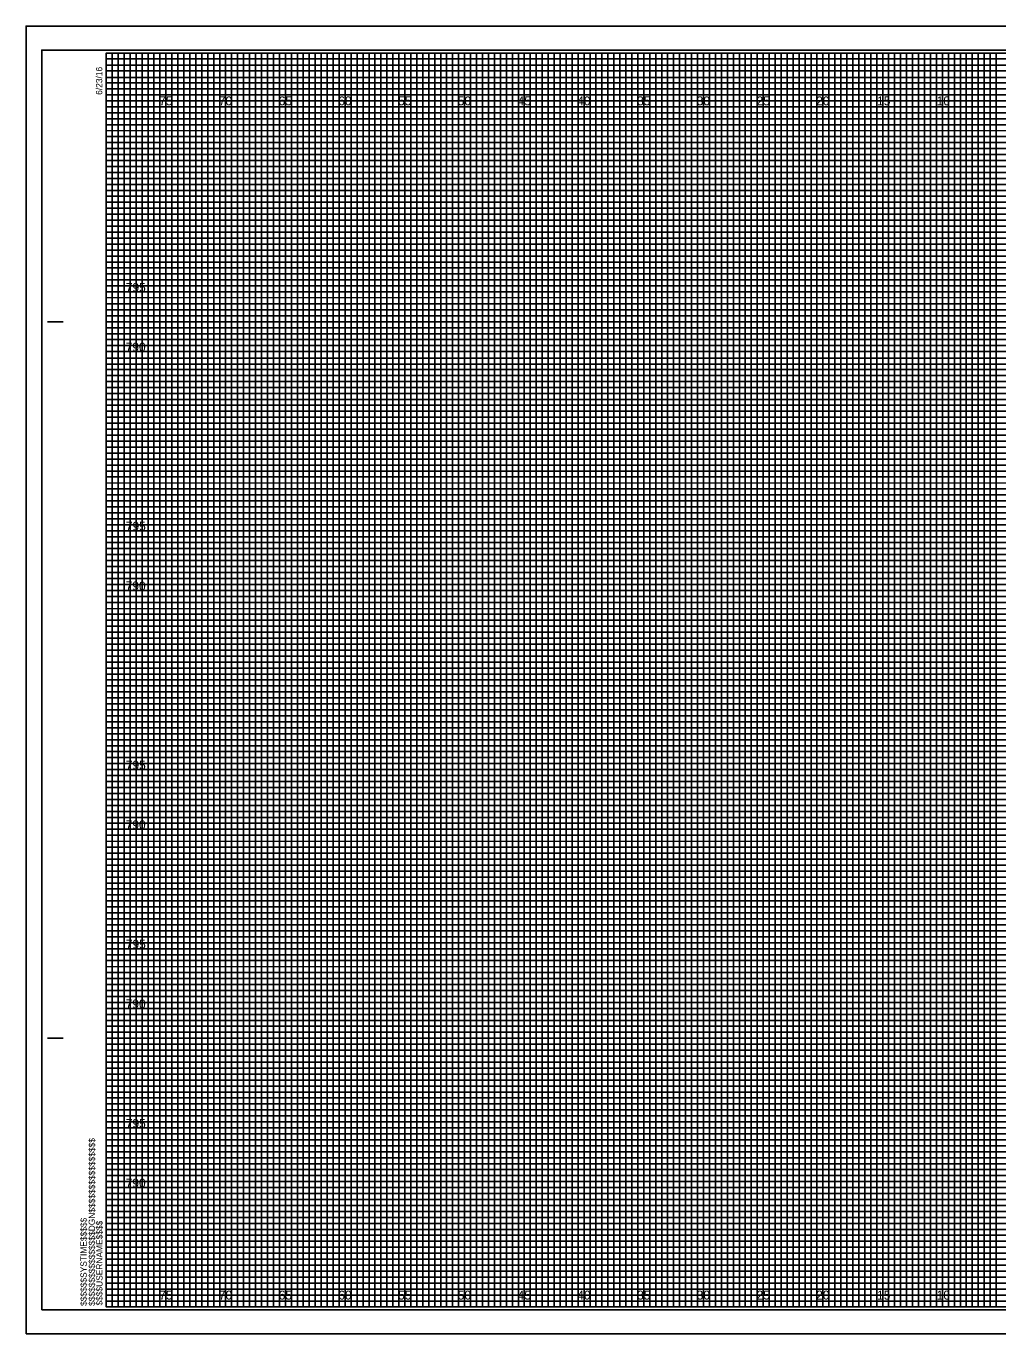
# Model space of a CAD drawing. Extents: x -7 to 162, y -2 to 107.
# Drawn here: x -6.7 to 74.6, y -2.3 to 107.3 of the extents above; entities that cross this region are included whole.
import ezdxf

# ---------------------------------------------------------------- set-up
doc = ezdxf.new("R2010")
doc.units = 0
for name, color, linetype in [('Exist Cross Section Cell', 7, 'Continuous'), ('Exist XS Center Line Elevation Label', 7, 'Continuous'), ('Prop CMT Pvmt Course 2 Wedge', 7, 'Continuous'), ('Prop XS Elevation Labels', 7, 'Continuous'), ('Prop XS Hydro Elevations', 7, 'Continuous'), ('Prop XS SE Text', 7, 'Continuous'), ('Prop XS Side Slope Text', 7, 'Continuous'), ('Sheet Cutting Line CELL', 7, 'Continuous'), ('Sheet DOT Grid CELL', 7, 'Continuous'), ('Sheet Plot Border Inside CELL', 7, 'Continuous'), ('Sheet Plot Border Outside CELL', 7, 'Continuous')]:
    doc.layers.add(name, color=color, linetype=linetype)

msp = doc.modelspace()

# ---------------------------------------------------------------- linework, layer by layer
at = {"layer": 'Exist Cross Section Cell'}
for p, q in [((5, 105), (0, 105)), ((5, 0), (5, 105)), ((15, 105), (10, 105)), ((10, 105), (10, 0)), ((15, 0), (15, 105)), ((25, 105), (20, 105)), ((20, 105), (20, 0)), ((25, 0), (25, 105)), ((35, 105), (30, 105)), ((30, 105), (30, 0)), ((35, 0), (35, 105)), ((45, 105), (40, 105)), ((40, 105), (40, 0)), ((45, 0), (45, 105)), ((55, 105), (50, 105)), ((50, 105), (50, 0)), ((55, 0), (55, 105)), ((65, 105), (60, 105)), ((60, 105), (60, 0)), ((65, 0), (65, 105)), ((75, 105), (70, 105)), ((70, 105), (70, 0)), ((10, 0), (5, 0)), ((20, 0), (15, 0)), ((30, 0), (25, 0)), ((40, 0), (35, 0)), ((50, 0), (45, 0)), ((60, 0), (55, 0)), ((70, 0), (65, 0))]:
    msp.add_line(p, q, dxfattribs=at)
for points in [[(0, 100), (160, 100), (160, 95), (0, 95)], [(0, 90), (160, 90), (160, 85), (0, 85)], [(0, 80), (160, 80), (160, 75), (0, 75)], [(0, 70), (160, 70), (160, 65), (0, 65)], [(0, 60), (160, 60), (160, 55), (0, 55)], [(0, 50), (160, 50), (160, 45), (0, 45)], [(0, 40), (160, 40), (160, 35), (0, 35)], [(0, 30), (160, 30), (160, 25), (0, 25)], [(0, 20), (160, 20), (160, 15), (0, 15)], [(0, 10), (160, 10), (160, 5), (0, 5)]]:
    msp.add_lwpolyline(points, dxfattribs=at)
at = {"layer": 'Exist XS Center Line Elevation Label'}
for points in [[(0, 105), (2.5, 105), (2.5, 0), (7.5, 0), (7.5, 105), (12.5, 105), (12.5, 0), (17.5, 0), (17.5, 105), (22.5, 105), (22.5, 0), (27.5, 0), (27.5, 105), (32.5, 105), (32.5, 0), (37.5, 0), (37.5, 105), (42.5, 105), (42.5, 0), (47.5, 0), (47.5, 105), (52.5, 105), (52.5, 0), (57.5, 0), (57.5, 105), (62.5, 105), (62.5, 0), (67.5, 0), (67.5, 105), (72.5, 105), (72.5, 0), (77.5, 0)], [(0, 102.5), (137.5, 102.5)], [(0, 92.5), (160, 92.5), (160, 97.5), (0, 97.5)], [(0, 82.5), (160, 82.5), (160, 87.5), (0, 87.5)], [(0, 72.5), (160, 72.5), (160, 77.5), (0, 77.5)], [(0, 62.5), (160, 62.5), (160, 67.5), (0, 67.5)], [(0, 52.5), (160, 52.5), (160, 57.5), (0, 57.5)], [(0, 42.5), (160, 42.5), (160, 47.5), (0, 47.5)], [(0, 32.5), (160, 32.5), (160, 37.5), (0, 37.5)], [(0, 22.5), (160, 22.5), (160, 27.5), (0, 27.5)], [(0, 12.5), (160, 12.5), (160, 17.5), (0, 17.5)], [(0, 2.5), (160, 2.5), (160, 7.5), (0, 7.5)]]:
    msp.add_lwpolyline(points, dxfattribs=at)
at = {"layer": 'Prop CMT Pvmt Course 2 Wedge'}
for points in [[(0, 0), (0.5, 0), (0.5, 105), (1, 105), (1, 0)], [(1, 0), (1.5, 0), (1.5, 105), (2, 105), (2, 0)], [(2.5, 0), (3, 0), (3, 105), (3.5, 105), (3.5, 0)], [(3.5, 0), (4, 0), (4, 105), (4.5, 105), (4.5, 0)], [(5, 0), (5.5, 0), (5.5, 105), (6, 105), (6, 0)], [(6, 0), (6.5, 0), (6.5, 105), (7, 105), (7, 0)], [(7.5, 0), (8, 0), (8, 105), (8.5, 105), (8.5, 0)], [(8.5, 0), (9, 0), (9, 105), (9.5, 105), (9.5, 0)], [(10, 0), (10.5, 0), (10.5, 105), (11, 105), (11, 0)], [(11, 0), (11.5, 0), (11.5, 105), (12, 105), (12, 0)], [(12.5, 0), (13, 0), (13, 105), (13.5, 105), (13.5, 0)], [(13.5, 0), (14, 0), (14, 105), (14.5, 105), (14.5, 0)], [(15, 0), (15.5, 0), (15.5, 105), (16, 105), (16, 0)], [(16, 0), (16.5, 0), (16.5, 105), (17, 105), (17, 0)], [(17.5, 0), (18, 0), (18, 105), (18.5, 105), (18.5, 0)], [(18.5, 0), (19, 0), (19, 105), (19.5, 105), (19.5, 0)], [(20, 0), (20.5, 0), (20.5, 105), (21, 105), (21, 0)], [(21, 0), (21.5, 0), (21.5, 105), (22, 105), (22, 0)], [(22.5, 0), (23, 0), (23, 105), (23.5, 105), (23.5, 0)], [(23.5, 0), (24, 0), (24, 105), (24.5, 105), (24.5, 0)], [(25, 0), (25.5, 0), (25.5, 105), (26, 105), (26, 0)], [(26, 0), (26.5, 0), (26.5, 105), (27, 105), (27, 0)], [(27.5, 0), (28, 0), (28, 105), (28.5, 105), (28.5, 0)], [(28.5, 0), (29, 0), (29, 105), (29.5, 105), (29.5, 0)], [(30, 0), (30.5, 0), (30.5, 105), (31, 105), (31, 0)], [(31, 0), (31.5, 0), (31.5, 105), (32, 105), (32, 0)], [(32.5, 0), (33, 0), (33, 105), (33.5, 105), (33.5, 0)], [(33.5, 0), (34, 0), (34, 105), (34.5, 105), (34.5, 0)], [(35, 0), (35.5, 0), (35.5, 105), (36, 105), (36, 0)], [(36, 0), (36.5, 0), (36.5, 105), (37, 105), (37, 0)], [(37.5, 0), (38, 0), (38, 105), (38.5, 105), (38.5, 0)], [(38.5, 0), (39, 0), (39, 105), (39.5, 105), (39.5, 0)], [(40, 0), (40.5, 0), (40.5, 105), (41, 105), (41, 0)], [(41, 0), (41.5, 0), (41.5, 105), (42, 105), (42, 0)], [(42.5, 0), (43, 0), (43, 105), (43.5, 105), (43.5, 0)], [(43.5, 0), (44, 0), (44, 105), (44.5, 105), (44.5, 0)], [(45, 0), (45.5, 0), (45.5, 105), (46, 105), (46, 0)], [(46, 0), (46.5, 0), (46.5, 105), (47, 105), (47, 0)], [(47.5, 0), (48, 0), (48, 105), (48.5, 105), (48.5, 0)], [(48.5, 0), (49, 0), (49, 105), (49.5, 105), (49.5, 0)], [(50, 0), (50.5, 0), (50.5, 105), (51, 105), (51, 0)], [(51, 0), (51.5, 0), (51.5, 105), (52, 105), (52, 0)], [(52.5, 0), (53, 0), (53, 105), (53.5, 105), (53.5, 0)], [(53.5, 0), (54, 0), (54, 105), (54.5, 105), (54.5, 0)], [(55, 0), (55.5, 0), (55.5, 105), (56, 105), (56, 0)], [(56, 0), (56.5, 0), (56.5, 105), (57, 105), (57, 0)], [(57.5, 0), (58, 0), (58, 105), (58.5, 105), (58.5, 0)], [(58.5, 0), (59, 0), (59, 105), (59.5, 105), (59.5, 0)], [(60, 0), (60.5, 0), (60.5, 105), (61, 105), (61, 0)], [(61, 0), (61.5, 0), (61.5, 105), (62, 105), (62, 0)], [(62.5, 0), (63, 0), (63, 105), (63.5, 105), (63.5, 0)], [(63.5, 0), (64, 0), (64, 105), (64.5, 105), (64.5, 0)], [(65, 0), (65.5, 0), (65.5, 105), (66, 105), (66, 0)], [(66, 0), (66.5, 0), (66.5, 105), (67, 105), (67, 0)], [(67.5, 0), (68, 0), (68, 105), (68.5, 105), (68.5, 0)], [(68.5, 0), (69, 0), (69, 105), (69.5, 105), (69.5, 0)], [(70, 0), (70.5, 0), (70.5, 105), (71, 105), (71, 0)], [(71, 0), (71.5, 0), (71.5, 105), (72, 105), (72, 0)], [(72.5, 0), (73, 0), (73, 105), (73.5, 105), (73.5, 0)], [(73.5, 0), (74, 0), (74, 105), (74.5, 105), (74.5, 0)]]:
    msp.add_lwpolyline(points, dxfattribs=at)
at = {"layer": 'Prop XS Hydro Elevations'}
for p, q in [((-4.9, 82.5), (-3.65, 82.5)), ((-4.85, 82.5), (-3.6, 82.5)), ((-4.9, 22.5), (-3.65, 22.5)), ((-4.85, 22.5), (-3.6, 22.5)), ((0, 0), (0, 0)), ((0, 0), (0, 0)), ((0, 0), (0, 0)), ((0, 0), (0, 0)), ((0, 0), (0, 0)), ((0, 0), (0, 0)), ((0, 0), (0, 0))]:
    msp.add_line(p, q, dxfattribs=at)
msp.add_lwpolyline([(160, 105), (0, 105), (0, 0), (160, 0)], close=True, dxfattribs=at)
at = {"layer": 'Prop XS Side Slope Text'}
for p, q in [((0, 104.5), (130, 104.5)), ((130, 103.99), (0, 103.99)), ((0, 103.99), (0, 103.5)), ((0, 103.5), (130, 103.5)), ((130, 102.95), (0, 102.95)), ((0, 102.95), (0, 102)), ((0, 102), (160, 102))]:
    msp.add_line(p, q, dxfattribs=at)
for points in [[(0, 101.5), (135, 101.5), (160, 101.5), (160, 101), (0, 101)], [(0, 100.5), (160, 100.5), (160, 99.5), (0, 99.5)], [(0, 99), (160, 99), (160, 98.5), (0, 98.49)], [(0, 98), (160, 98), (160, 97), (0, 97)], [(0, 96.5), (160, 96.5), (160, 96), (0, 96)], [(0, 95.5), (160, 95.5), (160, 94.5), (0, 94.5)], [(0, 94), (160, 94), (160, 93.5), (0, 93.5)], [(0, 93), (160, 93), (160, 92), (0, 92)], [(0, 91.5), (160, 91.5), (160, 91), (0, 91)], [(0, 90.5), (160, 90.5), (160, 89.5), (0, 89.5)], [(0, 89), (160, 89), (160, 88.5), (0, 88.5)], [(0, 88), (160, 88), (160, 86.98), (160, 86.5), (160, 86), (0, 86)], [(0, 87), (160, 87), (160, 86.5), (0, 86.5)], [(0, 85.5), (160, 85.5), (160, 84.5), (0, 84.52)], [(0, 84.52), (160, 84.5), (160, 84), (0, 84)], [(0, 83.5), (160, 83.5), (160, 83), (0, 83)], [(0, 82), (160, 82), (160, 81.5), (0, 81.5)], [(0, 81), (160, 81), (160, 80.5), (0, 80.5)], [(-0.04, 79.45), (160, 79.45), (160, 78.94), (-0.04, 78.94)], [(0, 78.5), (160, 78.5), (160, 78), (0, 78)], [(0, 77), (160, 77), (160, 76.5), (0, 76.5)], [(0, 76), (160, 76), (160, 75.5), (0, 75.5)], [(0, 74.5), (160, 74.5), (160, 74), (0, 74)], [(0, 73.5), (160, 73.5), (160, 73), (0, 73)], [(0, 72), (160, 72), (160, 71.5), (0, 71.5)], [(0, 71), (160, 71), (160, 70.5), (0, 70.5)], [(0, 69.5), (160, 69.5), (160, 68.99), (0, 69)], [(0, 68.5), (160, 68.5), (160, 68), (0, 68)], [(0, 67), (160, 67), (160, 66.5), (0, 66.5)], [(0, 66), (160, 66), (160, 65.5), (0, 65.5)], [(0, 64.5), (160, 64.5), (160, 64), (0, 64)], [(0, 63.5), (160, 63.5), (160, 63), (0, 63)], [(0, 62), (160, 62), (160, 61.5), (0, 61.5)], [(0, 61), (160, 61), (160, 60.5), (0, 60.5)], [(0, 59.5), (160, 59.5), (160, 59), (0, 59)], [(0, 58.5), (160.03, 58.45), (160, 58), (0, 58)], [(0, 57), (160, 57), (160, 56.5), (0, 56.5)], [(0, 56), (160, 56), (160, 55.5), (0, 55.5)], [(0, 54.5), (160, 54.5), (160, 54), (0, 54)], [(0, 53.5), (160, 53.5), (160, 53), (0, 53)], [(0, 52), (160, 52), (160, 51.5), (0, 51.5)], [(0, 51), (160, 51), (160, 50.5), (0, 50.5)], [(0, 49.5), (160, 49.5), (160, 49), (0, 49)], [(0, 48.5), (160, 48.5), (160, 48), (0, 48)], [(0, 47), (160, 47), (160, 46.5), (0, 46.5)], [(0, 46), (160, 46), (160, 45.5), (0, 45.5)], [(0, 44.5), (160, 44.5), (160, 44), (0, 44)], [(0, 43.5), (160, 43.5), (160, 43), (0, 43)], [(0, 42), (160, 42), (160, 41.5), (0, 41.5)], [(0, 41), (160, 41), (160, 40.5), (0, 40.5)], [(0, 39.5), (160, 39.5), (160, 38.99), (0, 39)], [(0, 38.5), (160, 38.5), (160, 38), (0, 38)], [(0, 37), (160, 37), (160, 36.5), (0, 36.5)], [(0, 36), (160, 36), (160, 35.5), (0, 35.5)], [(0, 34.5), (160, 34.5), (160, 34), (0, 34)], [(0, 33.5), (160, 33.5), (160, 33), (0, 33)], [(0, 32), (160, 32), (160, 31.5), (0, 31.5)], [(0, 31), (160, 31), (160, 30.5), (0, 30.5)], [(0, 29.5), (160, 29.5), (160, 29), (0, 29)], [(0, 28.5), (160.03, 28.46), (160, 28), (0, 28)], [(0, 27), (160, 27), (160, 26.5), (0, 26.5)], [(0, 26), (160, 26), (160, 25.5), (0, 25.5)], [(0, 24.5), (160, 24.5), (160, 24), (0, 24)], [(0, 23.5), (160, 23.5), (160, 23), (0, 23)], [(0, 22), (160, 22), (160, 21.5), (0, 21.5)], [(0, 21), (160, 21), (160, 20.5), (0, 20.5)], [(0, 19.5), (160, 19.5), (160, 19), (0, 19)], [(0, 18.5), (160, 18.5), (160, 18), (0, 18)], [(0, 17), (160, 17), (160, 16.5), (0, 16.5)], [(0, 16), (160, 16), (160, 15.5), (0, 15.5)], [(0, 14.5), (160, 14.5), (160, 14), (0, 14)], [(0, 13.5), (160, 13.5), (160, 13), (0, 13)], [(0, 12), (160, 12), (160, 11.5), (0, 11.5)], [(0, 11), (160, 11), (160, 10.5), (0, 10.5)], [(0, 9.5), (160, 9.5), (160, 9), (0, 9)], [(0, 8.5), (160, 8.5), (160, 8), (0, 8)], [(0, 7), (160, 7), (160, 6.5), (0, 6.5)], [(0, 6), (160, 6), (160, 5.5), (0, 5.5)], [(0, 4.5), (160, 4.5), (160, 4), (0, 4)], [(0, 3.5), (160, 3.5), (160, 3), (0, 3)], [(0, 2), (160, 2), (160, 1.5), (0, 1.5)], [(0, 1), (160, 1), (160, 0.5), (0, 0.5)]]:
    msp.add_lwpolyline(points, dxfattribs=at)
at = {"layer": 'Sheet Cutting Line CELL'}
for p, q in [((161.65, 107.25), (-6.7, 107.25)), ((-6.7, 107.25), (-6.7, -2.25)), ((-6.7, -2.25), (161.65, -2.25))]:
    msp.add_line(p, q, dxfattribs=at)
at = {"layer": 'Sheet DOT Grid CELL'}
for p, q in [((5, 0), (5, 105)), ((10, 0), (10, 105)), ((15, 0), (15, 105)), ((20, 0), (20, 105)), ((25, 0), (25, 105)), ((30, 0), (30, 105)), ((35, 0), (35, 105)), ((40, 0), (40, 105)), ((45, 0), (45, 105)), ((50, 0), (50, 105)), ((55, 0), (55, 105)), ((60, 0), (60, 105)), ((65, 0), (65, 105)), ((70, 0), (70, 105)), ((0, 100), (160, 100)), ((0, 95), (160, 95)), ((0, 90), (160, 90)), ((0, 85), (160, 85)), ((0, 80), (160, 80)), ((0, 75), (160, 75)), ((0, 70), (160, 70)), ((0, 65), (160, 65)), ((0, 60), (160, 60)), ((0, 55), (160, 55)), ((0, 50), (160, 50)), ((0, 45), (160, 45)), ((0, 40), (160, 40)), ((0, 35), (160, 35)), ((0, 30), (160, 30)), ((0, 25), (160, 25)), ((0, 20), (160, 20)), ((0, 15), (160, 15)), ((0, 10), (160, 10)), ((0, 5), (160, 5))]:
    msp.add_line(p, q, dxfattribs=at)
at = {"layer": 'Sheet Plot Border Inside CELL'}
msp.add_lwpolyline([(-5.4, -0.25), (161.2, -0.25), (161.2, 105.25), (-5.4, 105.25)], close=True, dxfattribs=at)
at = {"layer": 'Sheet Plot Border Outside CELL'}
msp.add_lwpolyline([(-6.7, -2.25), (161.65, -2.25), (161.65, 107.25), (-6.7, 107.25)], close=True, dxfattribs=at)

# ---------------------------------------------------------------- texts
at = {"layer": 'Prop XS Elevation Labels'}
for s, p in [('795', (1.64, 85)), ('790', (1.63, 80)), ('795', (1.64, 65)), ('790', (1.63, 60)), ('795', (1.64, 45)), ('790', (1.63, 40)), ('795', (1.64, 30)), ('790', (1.63, 25)), ('795', (1.64, 15)), ('790', (1.63, 10))]:
    msp.add_text(s, height=0.75, dxfattribs=at).set_placement(p)
at = {"layer": 'Prop XS Hydro Elevations'}
for s, p in [('6/23/16', (-0.33, 101.5)), ('$$$$$$$$$$$$$$$$DGN$$$$$$$$$$$$$$$$', (-0.94, 0.09)), ('$$$$$$SYSTIME$$$$$', (-1.63, 0.09)), ('$$$$USERNAME$$$$', (-0.31, 0.12))]:
    msp.add_text(s, height=0.525, rotation=90, dxfattribs=at).set_placement(p)
at = {"layer": 'Prop XS SE Text'}
for s, p in [('75', (4.44, 100.62)), ('70', (9.43, 100.62)), ('65', (14.44, 100.62)), ('60', (19.43, 100.62)), ('55', (24.44, 100.62)), ('50', (29.43, 100.62)), ('45', (34.44, 100.62)), ('40', (39.43, 100.62)), ('35', (44.44, 100.62)), ('30', (49.43, 100.62)), ('25', (54.44, 100.62)), ('20', (59.43, 100.62)), ('15', (64.53, 100.62)), ('10', (69.52, 100.62)), ('75', (4.44, 0.62)), ('70', (9.43, 0.62)), ('65', (14.44, 0.62)), ('60', (19.43, 0.62)), ('55', (24.44, 0.62)), ('50', (29.43, 0.62)), ('45', (34.44, 0.62)), ('40', (39.43, 0.62)), ('35', (44.44, 0.62)), ('30', (49.43, 0.62)), ('25', (54.44, 0.62)), ('20', (59.43, 0.62)), ('15', (64.53, 0.62)), ('10', (69.52, 0.62))]:
    msp.add_text(s, height=0.75, dxfattribs=at).set_placement(p)

doc.saveas('drawing.dxf')
